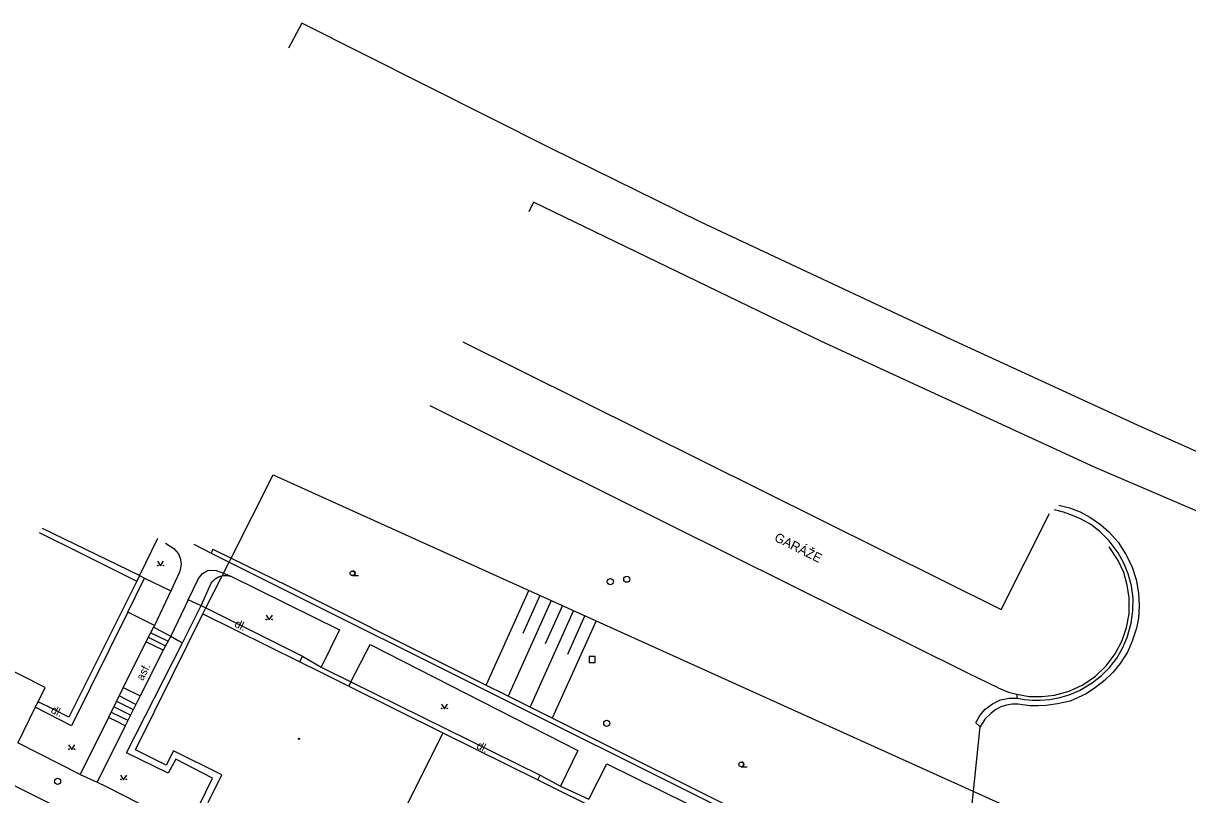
# Model space of a CAD drawing. Extents: x -602419 to -601554, y -1162937 to -1162362.
# Drawn here: x -602127.5 to -602032.9, y -1162429.2 to -1162366.6 of the extents above; entities that cross this region are included whole.
import ezdxf

# ---------------------------------------------------------------- set-up
doc = ezdxf.new("R2010")
doc.units = 0
doc.layers.add('Podklad', color=7, linetype='Continuous')

msp = doc.modelspace()

# ---------------------------------------------------------------- linework, layer by layer
at = {"layer": 'Podklad'}
for p, q in [((-602100.74, -1162411.4475), (-602100.24, -1162411.4475)), ((-602069.15, -1162426.9775), (-602068.65, -1162426.9775))]:
    msp.add_line(p, q, dxfattribs=at)
for points in [[(-601981.359, -1162423.886), (-601980.675, -1162421.822), (-601993.665, -1162417.388), (-601998.487, -1162415.733), (-602004.099, -1162413.377), (-602022.511, -1162405.666), (-602036.956, -1162399.221), (-602052.146, -1162392.22), (-602072.492, -1162382.698), (-602084.592, -1162376.742), (-602104.849, -1162366.563), (-602105.932, -1162368.585)], [(-602002.95, -1162418.7), (-602040.4, -1162402.67), (-602062.69, -1162392.39), (-602086.01, -1162381.11), (-602086.4099, -1162381.89)], [(-602091.75, -1162392.45), (-602048.02, -1162414.19)], [(-602050.62, -1162419.43), (-602094.4099, -1162397.64)], [(-602110.59, -1162410.03), (-602107.1599, -1162403.26)], [(-602107.1599, -1162403.26), (-602014, -1162445.37)], [(-602050.09, -1162423.4099), (-602049.76, -1162422.82), (-602049.33, -1162422.29), (-602048.74, -1162421.87), (-602048.09, -1162421.55), (-602047.38, -1162421.4099), (-602046.75, -1162421.4099), (-602046.12, -1162421.51), (-602045.49, -1162421.57), (-602044.86, -1162421.58), (-602044.06, -1162421.51), (-602043.27, -1162421.36), (-602042.49, -1162421.14), (-602041.6599, -1162420.77), (-602040.62, -1162420.15), (-602039.88, -1162419.56), (-602039.21, -1162418.9), (-602038.64, -1162418.15), (-602038.17, -1162417.33), (-602037.78, -1162416.4699), (-602037.46, -1162415.3), (-602037.32, -1162414.3), (-602037.31, -1162413.29), (-602037.44, -1162412.28), (-602037.7199, -1162411.31), (-602038.09, -1162410.37), (-602038.51, -1162409.59), (-602039.26, -1162408.61), (-602040.02, -1162407.86), (-602040.73, -1162407.3), (-602041.52, -1162406.87), (-602042.23, -1162406.55), (-602042.96, -1162406.28), (-602043.7, -1162406.1)], [(-602043.35, -1162405.71), (-602042.4699, -1162405.95), (-602041.62, -1162406.26), (-602040.82, -1162406.7), (-602039.96, -1162407.28), (-602039.28, -1162407.9), (-602038.53, -1162408.74), (-602037.9099, -1162409.68), (-602037.4099, -1162410.69), (-602037.05, -1162411.76), (-602036.86, -1162412.87), (-602036.8, -1162413.88), (-602036.87, -1162414.9), (-602037.04, -1162415.71), (-602037.37, -1162416.76), (-602037.76, -1162417.6599), (-602038.36, -1162418.6), (-602038.94, -1162419.33), (-602039.62, -1162419.9699), (-602040.35, -1162420.55), (-602041.13, -1162421.05), (-602042.4099, -1162421.64), (-602043.45, -1162421.87), (-602044.37, -1162422.01), (-602045.02, -1162422.03), (-602045.6599, -1162422.02), (-602046.3, -1162421.94), (-602046.64, -1162421.89), (-602047.12, -1162421.9), (-602047.59, -1162421.98), (-602048.04, -1162422.12), (-602048.4699, -1162422.33), (-602048.85, -1162422.61), (-602049.35, -1162423.11), (-602049.7199, -1162423.74)], [(-602048.02, -1162414.19), (-602044.09, -1162406.4099)], [(-602126.18, -1162407.93), (-602122.92, -1162409.56)], [(-602125.95, -1162407.58), (-602118.07, -1162411.42), (-602118.03, -1162411.44)], [(-602116.57, -1162408.44), (-602118.03, -1162411.44)], [(-602115.92, -1162408.82), (-602115.25, -1162409.23), (-602114.87, -1162409.68), (-602114.73, -1162410.03), (-602114.6599, -1162410.5), (-602114.69, -1162410.84), (-602114.77, -1162411.1599)], [(-602113.61, -1162408.9), (-602112.2199, -1162409.61)], [(-602122.92, -1162409.56), (-602118.25, -1162411.9)], [(-602112.07, -1162409.31), (-602112.2199, -1162409.61), (-602110.75, -1162410.35)], [(-602112.07, -1162409.31), (-602110.59, -1162410.03)], [(-602038.51, -1162410.2199), (-602039.25, -1162409.12)], [(-602116.57, -1162410.2849), (-602116.32, -1162410.6599), (-602116.07, -1162410.2849)], [(-602111.31, -1162411.45), (-602110.75, -1162410.35)], [(-602110.75, -1162410.35), (-602110.59, -1162410.03)], [(-602110.75, -1162410.35), (-602085.9699, -1162422.74), (-602065.88, -1162432.75)], [(-602110.59, -1162410.03), (-602105.99, -1162412.28), (-602092.51, -1162419.02), (-602085.79, -1162422.38), (-602065.86, -1162432.31), (-602062.11, -1162430.76), (-602051.04, -1162436.18), (-602050.17, -1162439.85), (-602040.49, -1162444.95), (-602033.93, -1162447.87), (-602033.51, -1162450.86), (-602033.9099, -1162450.92)], [(-602038.07, -1162411.19), (-602038.51, -1162410.2199)], [(-602118.99, -1162414.42), (-602117.62, -1162411.64)], [(-602118.03, -1162411.44), (-602118.25, -1162411.9)], [(-602118.03, -1162411.44), (-602117.62, -1162411.64), (-602115.48, -1162412.68)], [(-602114.77, -1162411.1599), (-602115.48, -1162412.68)], [(-602114.0753, -1162413.4137), (-602113.228, -1162411.6677), (-602112.9132, -1162411.2632), (-602112.46, -1162411.0059), (-602111.799, -1162411.032), (-602111.2132, -1162411.2601), (-602110.55, -1162411.51)], [(-602112.64, -1162414.07), (-602111.31, -1162411.45)], [(-602112.2199, -1162412.07), (-602112.08, -1162411.89), (-602111.88, -1162411.71), (-602111.61, -1162411.55), (-602111.31, -1162411.45)], [(-602111.31, -1162411.45), (-602111.28, -1162411.44), (-602110.99, -1162411.43), (-602110.78, -1162411.45), (-602110.55, -1162411.51)], [(-602110.55, -1162411.51), (-602101.78, -1162415.86), (-602103.28, -1162418.89)], [(-602037.78, -1162412.21), (-602038.07, -1162411.19)], [(-602159.7199, -1162412.76), (-602157.26, -1162413.99), (-602151.36, -1162416.93), (-602126.27, -1162429.4699), (-602124.32, -1162430.46)], [(-602118.25, -1162411.9), (-602123.77, -1162422.94)], [(-602115.48, -1162412.68), (-602116.82, -1162415.49)], [(-602113.02, -1162413.88), (-602112.2199, -1162412.07)], [(-602086.4099, -1162412.64), (-602089.88, -1162420.33)], [(-602037.63, -1162413.26), (-602037.78, -1162412.21)], [(-602114.0753, -1162413.4137), (-602115.5, -1162416.37)], [(-602113.03, -1162413.89), (-602114.08, -1162413.41)], [(-602084.58, -1162413.4699), (-602088.09, -1162421.23)], [(-602085.5, -1162413.05), (-602086.89, -1162416.15)], [(-602037.62, -1162414.55), (-602037.63, -1162413.26)], [(-602116.82, -1162415.49), (-602118.99, -1162414.42), (-602123.55, -1162423.65), (-602126.5, -1162422.14)], [(-602115.33, -1162419.48), (-602112.88, -1162414.54)], [(-602114.55, -1162416.9), (-602113.02, -1162413.88)], [(-602113.02, -1162413.88), (-602112.64, -1162414.07)], [(-602112.88, -1162414.54), (-602112.64, -1162414.07)], [(-602112.88, -1162414.54), (-602105.01, -1162418.44)], [(-602112.64, -1162414.07), (-602104.79, -1162418)], [(-602107.74, -1162414.665), (-602107.49, -1162415.04), (-602107.24, -1162414.665)], [(-602082.76, -1162414.29), (-602086.3, -1162422.12)], [(-602083.67, -1162413.88), (-602085.08, -1162417)], [(-602037.84, -1162415.65), (-602037.62, -1162414.55)], [(-602116.9, -1162415.64), (-602117.52, -1162416.84)], [(-602116.82, -1162415.49), (-602116.9, -1162415.64)], [(-602116.9, -1162415.64), (-602115.5, -1162416.37)], [(-602080.94, -1162415.11), (-602084.51, -1162423.02)], [(-602081.85, -1162414.7), (-602083.27, -1162417.85)], [(-602117.32, -1162416.46), (-602115.9099, -1162417.14)], [(-602115.7199, -1162416.78), (-602117.13, -1162416.09)], [(-602115.5, -1162416.37), (-602116.1, -1162417.5)], [(-602115.5, -1162416.37), (-602114.88, -1162416.73), (-602114.55, -1162416.9)], [(-602038.19, -1162416.7199), (-602037.84, -1162415.65)], [(-602117.52, -1162416.84), (-602119.36, -1162420.55)], [(-602119.08, -1162425.86), (-602114.55, -1162416.9)], [(-602116.1, -1162417.5), (-602117.99, -1162421.2199)], [(-602116.1, -1162417.5), (-602117.52, -1162416.84)], [(-602100.85, -1162420.08), (-602099.3, -1162417.05), (-602082.4099, -1162425.65), (-602083.82, -1162428.56)], [(-602038.75, -1162417.8), (-602038.19, -1162416.7199)], [(-602105.01, -1162418.44), (-602104.79, -1162418)], [(-602105.01, -1162418.44), (-602103.42, -1162419.24)], [(-602104.79, -1162418), (-602103.28, -1162418.89)], [(-602039.49, -1162418.78), (-602038.75, -1162417.8)], [(-602125.69, -1162420.53), (-602129.63, -1162418.56)], [(-602103.42, -1162419.24), (-602101.02, -1162420.43)], [(-602103.28, -1162418.89), (-602100.85, -1162420.08)], [(-602040.37, -1162419.63), (-602039.49, -1162418.78)], [(-602118.37, -1162425.6), (-602115.33, -1162419.48)], [(-602100.85, -1162420.08), (-602101.02, -1162420.43)], [(-602100.85, -1162420.08), (-602085.49, -1162427.6599)], [(-602048.26, -1162420.56), (-602050.62, -1162419.43)], [(-602042.5, -1162420.83), (-602041.39, -1162420.31)], [(-602041.39, -1162420.31), (-602040.37, -1162419.63)], [(-602126.27, -1162421.69), (-602125.69, -1162420.53)], [(-602119.36, -1162420.55), (-602120.55, -1162422.9699)], [(-602118.33, -1162421.9099), (-602119.69, -1162421.2199)], [(-602119.36, -1162420.55), (-602117.99, -1162421.2199)], [(-602117.99, -1162421.2199), (-602119.2, -1162423.65)], [(-602101.02, -1162420.43), (-602093.39, -1162424.2199)], [(-602048.26, -1162420.56), (-602047.43, -1162420.9099)], [(-602047.43, -1162420.9099), (-602046.76, -1162421.09)], [(-602046.76, -1162421.09), (-602046.75, -1162421.41)], [(-602046.76, -1162421.09), (-602045.74, -1162421.26)], [(-602045.74, -1162421.26), (-602044.71, -1162421.26)], [(-602044.71, -1162421.26), (-602043.68, -1162421.1599)], [(-602043.68, -1162421.1599), (-602042.5, -1162420.83)], [(-602126.5, -1162422.14), (-602127.93, -1162425.03)], [(-602126.5, -1162422.14), (-602126.27, -1162421.69)], [(-602125.06, -1162422.29), (-602126.27, -1162421.69)], [(-602118.77, -1162422.78), (-602120.12, -1162422.1)], [(-602119.9, -1162421.65), (-602118.55, -1162422.33)], [(-602093.5, -1162421.885), (-602093.25, -1162422.26), (-602093, -1162421.885)], [(-602120.55, -1162422.9699), (-602122.85, -1162427.6), (-602127.93, -1162425.03)], [(-602123.77, -1162422.94), (-602125.06, -1162422.29)], [(-602119.2, -1162423.65), (-602119.81, -1162423.34), (-602120.55, -1162422.9699)], [(-602120.33, -1162422.53), (-602118.98, -1162423.2)], [(-602119.2, -1162423.65), (-602121.46, -1162428.23), (-602120.73, -1162428.59), (-602115.38, -1162431.32), (-602114.92, -1162431.02), (-602114.02, -1162431.48), (-602113.94, -1162432), (-602106.89, -1162435.57)], [(-602051.04, -1162436.18), (-602050.2751, -1162428.9729), (-602049.7199, -1162423.74)], [(-602049.7199, -1162423.74), (-602050.09, -1162423.4099)], [(-602093.39, -1162424.2199), (-602098.9, -1162435.31)], [(-602093.39, -1162424.2199), (-602085.68, -1162428.04)], [(-602123.79, -1162425.195), (-602123.54, -1162425.57), (-602123.29, -1162425.195)], [(-602115.71, -1162427.51), (-602119.08, -1162425.86)], [(-602116.69, -1162426.44), (-602118.37, -1162425.6)], [(-602115.28, -1162425.68), (-602115.86, -1162426.85)], [(-602111.34, -1162427.64), (-602115.28, -1162425.68)], [(-602115.86, -1162426.85), (-602116.69, -1162426.44)], [(-602115.08, -1162426.35), (-602115.71, -1162427.51)], [(-602112.1, -1162427.9099), (-602115.08, -1162426.35)], [(-602081.53, -1162429.62), (-602080.07, -1162426.74), (-602062.63, -1162435.36), (-602064.21, -1162438.3)], [(-602122.85, -1162427.6), (-602121.46, -1162428.23)], [(-602119.57, -1162427.655), (-602119.32, -1162428.03), (-602119.07, -1162427.655)], [(-602113.18, -1162430.12), (-602112.1, -1162427.9099)], [(-602112.46, -1162429.88), (-602111.34, -1162427.64)], [(-602085.68, -1162428.04), (-602085.49, -1162427.6599)], [(-602085.49, -1162427.6599), (-602083.82, -1162428.56)], [(-602085.68, -1162428.04), (-602084, -1162428.88)], [(-602084, -1162428.88), (-602081.74, -1162430)], [(-602083.82, -1162428.56), (-602081.53, -1162429.62)]]:
    msp.add_lwpolyline(points, dxfattribs=at)
msp.add_lwpolyline([(-602081.51, -1162418.51), (-602081.01, -1162418.51), (-602081.01, -1162418.01), (-602081.51, -1162418.01)], close=True, dxfattribs=at)
for centre, radius in [((-602116.5451, -1162410.6348), 0.025), ((-602116.0954, -1162410.6348), 0.025), ((-602100.74, -1162411.2598), 0.1875), ((-602079.78, -1162411.94), 0.25), ((-602078.44, -1162411.74), 0.25), ((-602107.7151, -1162415.0149), 0.025), ((-602107.2654, -1162415.0149), 0.025), ((-602093.4751, -1162422.2349), 0.025), ((-602093.0254, -1162422.2349), 0.025), ((-602080.07, -1162423.45), 0.25), ((-602105.07, -1162424.71), 0.045), ((-602105.07, -1162424.71), 0.0199), ((-602123.7651, -1162425.5449), 0.025), ((-602123.3154, -1162425.5449), 0.025), ((-602069.15, -1162426.7898), 0.1875), ((-602124.69, -1162428.1599), 0.25), ((-602119.5451, -1162428.0049), 0.025), ((-602119.0954, -1162428.0049), 0.025)]:
    msp.add_circle(centre, radius, dxfattribs=at)
for centre in [(-602100.6775, -1162411.2598), (-602069.0875, -1162426.7898)]:
    msp.add_arc(centre, 0.1875, 260.405931, 99.594069, dxfattribs=at)

# ---------------------------------------------------------------- texts
for s, height, rotation, p in [('GARÁŽE', 0.75, 333.53, (-602066.52, -1162408.59)), ('dl.', 0.65, 333.49, (-602110.37, -1162415.56)), ('asf.', 0.65, 63.07, (-602117.75, -1162420.03)), ('dl.', 0.65, 333.67, (-602125.29, -1162422.56)), ('dl.', 0.65, 333.49, (-602090.71, -1162425.46))]:
    msp.add_text(s, height=height, rotation=rotation, dxfattribs=at).set_placement(p)

doc.saveas('drawing.dxf')
